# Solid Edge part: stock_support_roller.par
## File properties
Title: Stock support roller
Author: Deepak Maini
Template: Normal.par
Last saved by: Robert a Rhodes jr
Revision: 9
Application: Solid Edge
Material: aluminum
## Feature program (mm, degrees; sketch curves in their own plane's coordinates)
sketch for "unnamed RevolvedProtrusion 1" plane through (0, 0, 0) normal (0, -1, 0) x-axis (1, 0, 0)
  line (60, 0) -> (60, 18.669)
  line (60, 18.669) -> (15.55, 18.669)
  line (15.55, 18.669) -> (15.55, 92.075)
  line (15.55, 92.075) -> (-2.2388, 92.075)
  line (-2.2388, 92.075) -> (-111.45, 29.0219)
  line (-220.6612, 92.075) -> (-111.45, 29.0219)
  line (-238.45, 92.075) -> (-220.6612, 92.075)
  line (-238.45, 18.669) -> (-238.45, 92.075)
  line (-282.9, 18.669) -> (-238.45, 18.669)
  line (-282.9, 0) -> (-282.9, 18.669)
revolve "unnamed RevolvedProtrusion 1" add full turn 360 deg about sketch line (-282.9, 0) -> (60, 0)
chamfer "unnamed Chamfer 1"
fillet "unnamed Round 1"
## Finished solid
Body 1: solid body, 14 faces, 13 edges, 0 vertices.
  Faces by surface: cone 4, cylinder 4, plane 4, torus 2
  Edges by curve: circle 13
Bounding box of the edges (mm; curved faces can reach further): 342.900 x 184.150 x 184.150, from (-282.9, -92.075, -92.075) to (60, 92.075, 92.075).
Cylindrical faces by radius (mm): R18.669 x2, R92.075 x2
Conical faces (half-angle, radius in mm at the cone's reference point): 30 deg R29.0219 x1, 30 deg R92.075 x1, 45 deg R17.0942 x1, 45 deg R18.669 x1
Toroidal faces (ring radius, tube radius in mm): R20.2438 r1.5748 x2
Planar faces by outward normal: +x 2, -x 2
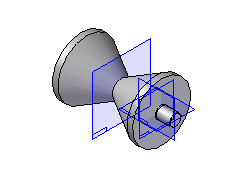
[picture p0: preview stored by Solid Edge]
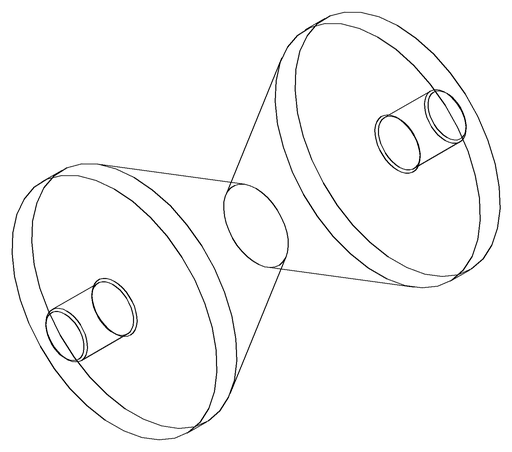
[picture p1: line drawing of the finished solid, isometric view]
